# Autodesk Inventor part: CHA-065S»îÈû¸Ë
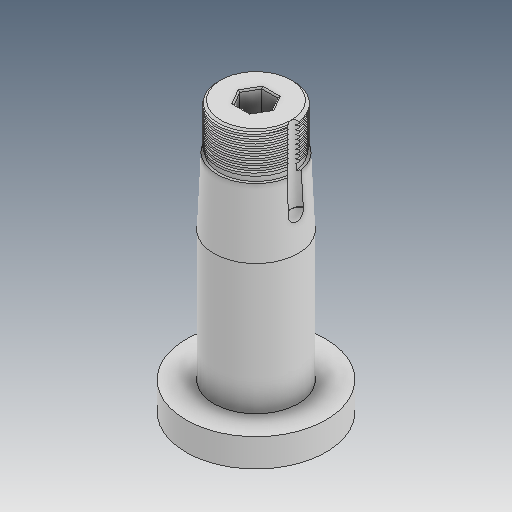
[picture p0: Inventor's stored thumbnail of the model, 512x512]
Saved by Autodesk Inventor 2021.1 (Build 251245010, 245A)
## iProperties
Created: 2019-05
Part Number: CHA-065S»îÈû¸Ë
Material: Ogólny
Document SubType Name: Modeling
Designer: user
Density: 1 g/cm^3
Appearance: Domyślna
Author: user
Revision Number: ÈÎºÎ
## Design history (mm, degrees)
feature "ÊäÈë1"
node "Bryła1"
